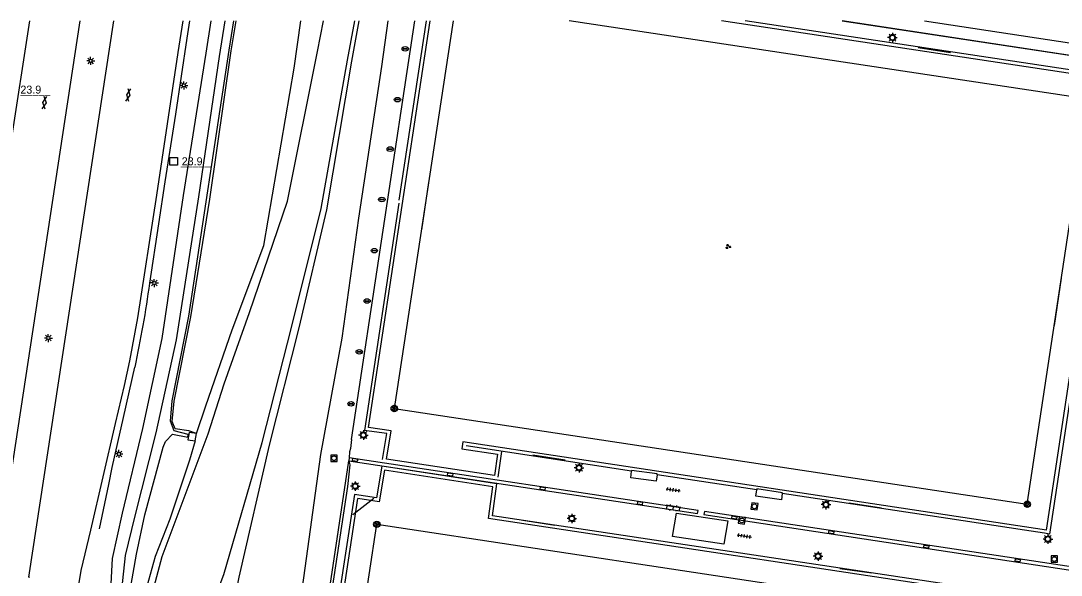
# Model space of a CAD drawing. Extents: x 125000 to 129004, y 397500 to 399008.
# Drawn here: x 126193.2 to 126355.6, y 398913.4 to 399000 of the extents above; entities that cross this region are included whole.
import ezdxf

# ---------------------------------------------------------------- set-up
doc = ezdxf.new("R2010")
doc.units = 0
for name, color, linetype in [('bs-afsc-ballenvanger', 7, 'Continuous'), ('bs-afsc-belijning', 7, 'Continuous'), ('bs-afsc-doel', 7, 'Continuous'), ('bs-afsc-hekwerk laag', 7, 'Continuous'), ('bs-afsc-poort', 7, 'Continuous'), ('bs-afsc-scorebord', 7, 'Continuous'), ('bs-symb-cornervlag', 7, 'Continuous'), ('bs-symb-veldverlichting', 7, 'Continuous'), ('gg-afsc-hekwerk', 7, 'Continuous'), ('gg-bbg-overig bouwwerk', 7, 'Continuous'), ('gg-knt-BGT kruinlijn', 7, 'Continuous'), ('gg-knt-bovenkant onderkant talud', 7, 'Continuous'), ('gg-knt-verharding', 7, 'Continuous'), ('gg-kntw-bovenkant insteek waterloop', 7, 'Continuous'), ('gg-kntw-waterlijn', 7, 'Continuous'), ('gg-kwrk-uitstroombak niveau min 01', 7, 'Continuous'), ('gt-anno-nummer hm paal', 7, 'Continuous'), ('gt-grn-groengrens', 7, 'Continuous'), ('gt-knt-geleideconstructie', 7, 'Continuous'), ('gt-symb-drainageput', 7, 'Continuous'), ('gt-symb-gesloten verharding', 7, 'Continuous'), ('gt-symb-groenvak', 7, 'Continuous'), ('gt-symb-hm paal', 7, 'Continuous'), ('gt-symb-klinker verharding', 7, 'Continuous'), ('gt-symb-kolk center center', 7, 'Continuous'), ('gt-symb-lichtmast', 7, 'Continuous'), ('gt-symb-rioolschacht', 7, 'Continuous'), ('gt-symb-tegel verharding', 7, 'Continuous')]:
    doc.layers.add(name, color=color, linetype=linetype)

# ---------------------------------------------------------------- blocks, each defined once
blk = doc.blocks.new('gt0-KOLKCC')
at = {"layer": 'gt-symb-kolk center center'}
blk.add_lwpolyline([(-0.38, 0.2), (0.37, 0.2), (0.37, -0.2), (-0.38, -0.2)], close=True, dxfattribs=at)
blk = doc.blocks.new('bs0-VELDV')
at = {"layer": 'bs-symb-veldverlichting'}
for p, q in [((-0.38, 0), (-0.75, 0)), ((-0.53, 0.53), (-0.27, 0.27)), ((-0.35, 0.14), (-0.52, 0.22)), ((-0.22, 0.52), (-0.14, 0.35)), ((0, 0.75), (0, 0.38)), ((0.22, 0.52), (0.14, 0.35)), ((0.27, 0.27), (0.53, 0.53)), ((0.35, 0.14), (0.52, 0.22)), ((0.38, 0), (0.75, 0)), ((-0.27, -0.27), (-0.53, -0.53)), ((-0.35, -0.14), (-0.52, -0.22)), ((-0.14, -0.35), (-0.22, -0.52)), ((0, -0.38), (0, -0.75)), ((0.14, -0.35), (0.22, -0.52)), ((0.27, -0.27), (0.53, -0.53)), ((0.35, -0.14), (0.52, -0.22))]:
    blk.add_line(p, q, dxfattribs=at)
blk.add_circle((0, 0), 0.375, dxfattribs=at)
blk = doc.blocks.new('gt0-RS')
at = {"layer": 'gt-symb-rioolschacht'}
blk.add_lwpolyline([(-0.5, -0.5), (0.5, -0.5), (0.5, 0.5), (-0.5, 0.5)], close=True, dxfattribs=at)
blk.add_circle((0, 0), 0.375, dxfattribs=at)
blk = doc.blocks.new('gt0-TEG1')
at = {"layer": 'gt-symb-tegel verharding'}
for p, q in [((-1.12, 0), (1.12, 0)), ((-0.9, -0.25), (-0.9, 0.25)), ((-0.45, -0.25), (-0.45, 0.25)), ((0, -0.25), (0, 0.25)), ((0.45, -0.25), (0.45, 0.25)), ((0.9, -0.25), (0.9, 0.25))]:
    blk.add_line(p, q, dxfattribs=at)
blk = doc.blocks.new('gt0-DPUT')
at = {"layer": 'gt-symb-drainageput'}
for p, q in [((-0.25, 0.05), (0.25, 0.05)), ((0.24, -0.05), (-0.25, -0.05))]:
    blk.add_line(p, q, dxfattribs=at)
for centre, radius, start, end in [((-0.25, 0), 0.0542, 85.4775, 270), ((0.24, 0), 0.0543, 269.9965, 85.474)]:
    blk.add_arc(centre, radius, start, end, dxfattribs=at)
blk.add_ellipse((0, 0), major_axis=(0.502, 0), ratio=0.705307, dxfattribs=at)
blk = doc.blocks.new('bs0-CORNVLG')
at = {"layer": 'bs-symb-cornervlag'}
for p, q in [((-0.34, 0.2), (0.2, -0.34)), ((-0.21, 0.35), (0.34, -0.2)), ((0.03, 0.4), (0.4, 0.03)), ((-0.4, -0.03), (-0.03, -0.4))]:
    blk.add_line(p, q, dxfattribs=at)
blk.add_circle((0, 0), 0.5, dxfattribs=at)
blk = doc.blocks.new('gt0-KL1')
at = {"layer": 'gt-symb-klinker verharding'}
for p, q in [((-1.15, 0.3), (1.15, 0.3)), ((-1, -0.3), (-1, 0.3)), ((-0.5, 0.3), (-0.5, 0.45)), ((0, -0.3), (0, 0.3)), ((0.5, 0.3), (0.5, 0.45)), ((1, -0.3), (1, 0.3)), ((-1.15, -0.3), (1.15, -0.3)), ((-0.5, -0.45), (-0.5, -0.3)), ((0.5, -0.45), (0.5, -0.3))]:
    blk.add_line(p, q, dxfattribs=at)
blk = doc.blocks.new('gt0-GRVAK')
at = {"layer": 'gt-symb-groenvak'}
for p, q in [((-0.11, 0.19), (-0.23, 0.24)), ((-0.18, 0.15), (0.09, 0.15)), ((-0.09, 0.21), (-0.16, 0.32)), ((-0.05, 0.21), (-0.05, 0.39)), ((0, 0.21), (0.06, 0.32)), ((0.01, 0.19), (0.13, 0.24)), ((0.26, -0.05), (0.2, 0.06)), ((0.3, -0.05), (0.3, 0.13)), ((0.35, -0.05), (0.41, 0.06)), ((-0.24, -0.23), (-0.36, -0.18)), ((-0.32, -0.26), (-0.05, -0.26)), ((-0.23, -0.21), (-0.29, -0.09)), ((-0.18, -0.2), (-0.18, -0.02)), ((-0.14, -0.21), (-0.07, -0.09)), ((-0.12, -0.23), (0, -0.18)), ((0.24, -0.07), (0.12, -0.02)), ((0.17, -0.11), (0.44, -0.11)), ((0.37, -0.07), (0.49, -0.02))]:
    blk.add_line(p, q, dxfattribs=at)
blk = doc.blocks.new('gt0-HMpaal')
at = {"layer": 'gt-symb-hm paal'}
blk.add_lwpolyline([(-0.6, 0.6), (0.6, 0.6), (0.6, -0.6), (-0.6, -0.6)], close=True, dxfattribs=at)
blk = doc.blocks.new('gt0-LMAST')
at = {"layer": 'gt-symb-lichtmast'}
for p, q in [((-0.18, 0.17), (-0.45, 0.44)), ((-0.01, 0.25), (-0.01, 0.62)), ((0.17, 0.17), (0.44, 0.44)), ((-0.26, 0), (-0.63, 0)), ((-0.18, -0.18), (-0.45, -0.45)), ((-0.01, -0.25), (-0.01, -0.63)), ((0.44, -0.45), (0.17, -0.18)), ((0.24, 0), (0.62, 0))]:
    blk.add_line(p, q, dxfattribs=at)
blk.add_circle((-0.01, 0), 0.25, dxfattribs=at)
blk = doc.blocks.new('gt0-GESVH1')
at = {"layer": 'gt-symb-gesloten verharding'}
for p, q in [((-0.99, -0.26), (0.01, 0.24)), ((0.01, -0.26), (-0.99, 0.24)), ((0.01, 0.24), (1.01, -0.26)), ((1.01, 0.24), (0.01, -0.26))]:
    blk.add_line(p, q, dxfattribs=at)

msp = doc.modelspace()

# ---------------------------------------------------------------- linework, layer by layer
at = {"layer": 'bs-afsc-ballenvanger'}
for p, q in [((126244.85, 398934.61), (126254.73, 399000)), ((126288.56, 398929.69), (126262.72, 398933.61)), ((126337.94, 398922.28), (126312.09, 398926.17))]:
    msp.add_line(p, q, dxfattribs=at)
for points in [[(126360.24, 398920.79), (126371.06, 398992.37), (126371.08, 398992.46), (126321.44, 399000)], [(126244.69, 398933.21), (126244.52, 398932.68), (126244.45, 398931.77), (126244.42, 398931.27), (126244.56, 398930.69), (126244.22, 398927.26), (126233.22, 398854.66)]]:
    msp.add_lwpolyline(points, dxfattribs=at)
at = {"layer": 'bs-afsc-belijning'}
for points in [[(126260.68, 399000), (126251.51, 398939.46), (126350.34, 398924.51), (126359.87, 398987.75), (126278.82, 399000)], [(126248.79, 398921.38), (126347.65, 398906.42), (126338, 398843.2), (126239.2, 398858.12), (126248.79, 398921.38)]]:
    msp.add_lwpolyline(points, dxfattribs=at)
at = {"layer": 'bs-afsc-doel'}
for p, q in [((126333.31, 398995.82), (126338.35, 398995.07)), ((126256.86, 398974.76), (126255.74, 398967.36)), ((126355.62, 398959.84), (126354.55, 398952.42)), ((126278.18, 398931.4), (126273.12, 398932.2)), ((126327.58, 398923.92), (126322.52, 398924.7)), ((126271.57, 398922.01), (126276.57, 398921.24)), ((126321.06, 398914.49), (126326.09, 398913.78))]:
    msp.add_line(p, q, dxfattribs=at)
at = {"layer": 'bs-afsc-hekwerk laag'}
for p, q in [((126252.28, 398972), (126256.53, 399000)), ((126252.22, 398971.55), (126246.85, 398936.03)), ((126268.26, 398932.77), (126267.66, 398928.76)), ((126308.1, 398926.78), (126292.53, 398929.11)), ((126242, 398904.04), (126245.34, 398926.03)), ((126349.88, 398920.46), (126337.94, 398922.28))]:
    msp.add_line(p, q, dxfattribs=at)
for points in [[(126359.21, 398955.62), (126364.59, 398991.18), (126306.3, 399000)], [(126359.15, 398955.2), (126353.8, 398919.85), (126353, 398919.98)], [(126249.69, 398931.51), (126250.37, 398935.54), (126246.82, 398936.05)], [(126352.26, 398909.83), (126266.82, 398922.73), (126267.52, 398927.71), (126249.56, 398930.47), (126248.74, 398925.52), (126245.32, 398926.01)]]:
    msp.add_lwpolyline(points, dxfattribs=at)
at = {"layer": 'bs-afsc-poort'}
for p, q in [((126244.85, 398934.61), (126244.69, 398933.21)), ((126353, 398919.98), (126349.88, 398920.46))]:
    msp.add_line(p, q, dxfattribs=at)
at = {"layer": 'bs-afsc-scorebord'}
msp.add_line((126248.34, 398925.4), (126245.02, 398922.88), dxfattribs=at)
at = {"layer": 'gg-afsc-hekwerk'}
for p, q in [((126244.85, 398934.61), (126254.73, 399000)), ((126321.44, 399000), (126371.08, 398992.46)), ((126244.85, 398934.61), (126244.69, 398933.21)), ((126244.52, 398932.68), (126244.45, 398931.77)), ((126244.69, 398933.21), (126244.52, 398932.68)), ((126244.45, 398931.77), (126244.42, 398931.27)), ((126244.42, 398931.27), (126244.56, 398930.69))]:
    msp.add_line(p, q, dxfattribs=at)
msp.add_lwpolyline([(126244.56, 398930.69), (126244.22, 398927.26), (126233.22, 398854.66)], dxfattribs=at)
at = {"layer": 'gg-bbg-overig bouwwerk'}
for points in [[(126292.53, 398929.11), (126292.4, 398928.11), (126288.43, 398928.62), (126288.56, 398929.69)], [(126292.53, 398929.11), (126292.54, 398929.24), (126288.57, 398929.76), (126288.56, 398929.69)], [(126312.09, 398926.17), (126311.95, 398925.19), (126307.96, 398925.79), (126308.1, 398926.78)], [(126312.09, 398926.17), (126312.11, 398926.32), (126308.12, 398926.93), (126308.1, 398926.78)], [(126303.56, 398921.91), (126302.96, 398918.29), (126294.97, 398919.49), (126295.57, 398923.11), (126303.56, 398921.91)]]:
    msp.add_lwpolyline(points, dxfattribs=at)
at = {"layer": 'gg-knt-BGT kruinlijn'}
for points in [[(126211.12, 398796.76), (126213.8, 398804.98), (126217.29, 398818.65), (126218.75, 398842.29), (126220.71, 398866.08), (126222.04, 398889.56), (126220.71, 398902.4), (126224.92, 398913.56), (126230.87, 398934.16), (126235.52, 398952.3), (126240.11, 398970.7), (126244.21, 398993.87), (126245.36, 399000)], [(126212.79, 398796.85), (126214.45, 398804.72), (126217.92, 398818.54), (126219.55, 398842.15), (126221.57, 398866.06), (126224.03, 398889.12), (126224.94, 398901.72), (126227.27, 398913.12), (126232.02, 398933.76), (126236.66, 398952.06), (126241, 398970.48), (126244.91, 398993.71), (126246.02, 399000)], [(126220.61, 398935.54), (126222.08, 398939.86), (126226.2, 398951.74), (126231.17, 398964.91), (126235.87, 398992.58), (126236.91, 399000)]]:
    msp.add_lwpolyline(points, dxfattribs=at)
at = {"layer": 'gg-knt-bovenkant onderkant talud'}
for points in [[(126204.12, 398801.18), (126207.27, 398807.9), (126210.77, 398815.47), (126211.54, 398819.18), (126211.15, 398842.84), (126211.31, 398866.36), (126211.15, 398890.1), (126212.52, 398897.68), (126212.58, 398906.21), (126215.25, 398916.33), (126222.46, 398935.51), (126224.93, 398943.33), (126228.92, 398954.45), (126234.85, 398971.83), (126239.51, 398995.23), (126240.48, 399000)], [(126220.17, 398796.67), (126221.21, 398803.52), (126223.59, 398817.57), (126227.06, 398840.65), (126230.5, 398865.35), (126232.89, 398887.78), (126236.04, 398900.78), (126237.19, 398911.52), (126240.04, 398932.3), (126243.4, 398950.47), (126246, 398969.2), (126249.56, 398992.89), (126250.56, 399000)]]:
    msp.add_lwpolyline(points, dxfattribs=at)
at = {"layer": 'gg-knt-verharding'}
for p, q in [((126191.65, 398980.76), (126194.59, 399000)), ((126247.49, 398936.52), (126257.14, 399000)), ((126232.65, 398853.51), (126244.42, 398931.27))]:
    msp.add_line(p, q, dxfattribs=at)
for points in [[(126189.19, 398913.89), (126189.31, 398913.86), (126202.47, 399000)], [(126194.6, 398913.09), (126194.48, 398913.11), (126207.72, 399000)], [(126202.26, 398911.93), (126202.63, 398914.18), (126204.12, 398920.45), (126207.99, 398937.14), (126209.4, 398943.06), (126210.24, 398946.92), (126211.46, 398953.61), (126214.44, 398972.78), (126217.78, 398995.05), (126218.54, 399000)], [(126353.35, 398920.49), (126363.94, 398990.71), (126302.62, 399000)], [(126353.35, 398920.49), (126262.21, 398934.27), (126262.05, 398933.17), (126267.64, 398932.33), (126267.15, 398928.99), (126250.29, 398931.53), (126251.02, 398935.97), (126247.49, 398936.52)], [(126244.42, 398931.27), (126298.86, 398923.05), (126298.94, 398923.54), (126244.45, 398931.77)], [(126351.64, 398909.37), (126266.2, 398922.29), (126266.9, 398927.24), (126250, 398929.81), (126249.17, 398924.89), (126245.83, 398925.4)], [(126351.64, 398909.37), (126340.99, 398839.15), (126235.21, 398855.23), (126245.83, 398925.4)], [(126359.25, 398914.42), (126299.92, 398923.4), (126299.86, 398922.9), (126359.17, 398913.93)]]:
    msp.add_lwpolyline(points, dxfattribs=at)
at = {"layer": 'gg-kntw-bovenkant insteek waterloop'}
for points in [[(126194.82, 398801.92), (126195.6, 398809.24), (126198.28, 398830.35), (126200.6, 398852.35), (126202.6, 398870.53), (126205.11, 398890.25), (126205.86, 398898.74), (126207.18, 398909.1), (126207.54, 398916.03), (126209.09, 398923.11), (126212.27, 398936.35), (126215.29, 398950.37), (126218.62, 398972.72), (126222.13, 398994.95), (126222.9, 399000)], [(126220.61, 398935.54), (126219.44, 398936), (126217.29, 398936.28), (126216.83, 398937.44), (126217.16, 398940.59), (126219.76, 398953.77), (126222.73, 398972.16), (126226.06, 398995.29), (126226.83, 399000)], [(126220.43, 398934.4), (126219.54, 398931.42), (126216.45, 398922.19), (126214.2, 398916.33), (126212.1, 398908.85), (126211.16, 398906.68), (126211, 398902.92), (126211.53, 398899.33), (126211.08, 398897.23), (126209.87, 398890.85), (126209.95, 398870.87), (126210.44, 398853.87), (126209.89, 398831.34), (126210.31, 398819.41), (126209.59, 398816.36), (126207.78, 398812.31), (126204.23, 398806.02)]]:
    msp.add_lwpolyline(points, dxfattribs=at)
at = {"layer": 'gg-kntw-waterlijn'}
for points in [[(126196.93, 398798.36), (126198, 398808.89), (126200.69, 398830.06), (126202.99, 398851.76), (126204.83, 398870.42), (126207.04, 398890.34), (126207.7, 398898.07), (126208.71, 398908.69), (126209.56, 398916.5), (126211, 398922.5), (126214.32, 398935.67), (126217.53, 398950.17), (126221, 398972.49), (126224.24, 398994.42), (126225.1, 399000)], [(126207.72, 398831.87), (126207.75, 398853.51), (126207.53, 398871.49), (126208.31, 398891.11), (126209.28, 398897.74), (126209.44, 398898.91), (126210.05, 398909.92), (126211.26, 398916.74), (126212.57, 398922.85), (126215.41, 398933.41), (126215.77, 398934.32), (126216.91, 398935.43), (126219.29, 398935.01), (126219.35, 398935.4), (126217.16, 398935.99), (126216.59, 398937.48), (126216.86, 398940.68), (126219.45, 398953.86), (126225.75, 398995.42), (126226.46, 399000)]]:
    msp.add_lwpolyline(points, dxfattribs=at)
at = {"layer": 'gg-kwrk-uitstroombak niveau min 01'}
msp.add_line((126220.43, 398934.4), (126220.61, 398935.54), dxfattribs=at)
msp.add_lwpolyline([(126220.61, 398935.54), (126219.48, 398935.74), (126219.29, 398934.59), (126220.43, 398934.4)], dxfattribs=at)
at = {"layer": 'gt-grn-groengrens'}
msp.add_line((126334.28, 399000), (126374.06, 398993.91), dxfattribs=at)
at = {"layer": 'gt-knt-geleideconstructie'}
for points in [[(126213.35, 398959.03), (126214.78, 398968.28), (126215.76, 398974.88), (126217.39, 398985.42), (126219.2, 398997.28), (126219.6, 399000)], [(126205.51, 398920.7), (126206.93, 398927.61), (126207.47, 398930.24), (126208.36, 398934.15), (126209.26, 398938.05), (126211.03, 398945.9)]]:
    msp.add_lwpolyline(points, dxfattribs=at)
msp.add_arc((126033.5, 398984.02), 181.58, 347.8817, 352.0884, dxfattribs=at)

# ---------------------------------------------------------------- block references
at = {"layer": 'bs-symb-cornervlag'}
for p in [(126251.51, 398939.46), (126350.34, 398924.51), (126248.79, 398921.38)]:
    msp.add_blockref('bs0-CORNVLG', p, dxfattribs=at)
at = {"layer": 'bs-symb-veldverlichting'}
for p in [(126329.28, 398997.37), (126246.69, 398935.32), (126280.35, 398930.22), (126245.42, 398927.34), (126318.9, 398924.45), (126279.23, 398922.29), (126353.55, 398919.08), (126317.67, 398916.41)]:
    msp.add_blockref('bs0-VELDV', p, dxfattribs=at)
at = {"layer": 'gt-symb-drainageput'}
for p in [(126253.22, 398995.62), (126252.02, 398987.69), (126250.87, 398979.97), (126249.57, 398972.1), (126248.4, 398964.11), (126247.26, 398956.24), (126246.05, 398948.32), (126244.76, 398940.2)]:
    msp.add_blockref('gt0-DPUT', p, dxfattribs=at)
at = {"layer": 'gt-symb-gesloten verharding'}
for p, rotation in [((126210, 398988.42), -99.72596567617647), ((126196.91, 398987.22), -98.10579358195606)]:
    msp.add_blockref('gt0-GESVH1', p, dxfattribs=dict(at, rotation=rotation))
at = {"layer": 'gt-symb-groenvak'}
msp.add_blockref('gt0-GRVAK', (126303.63, 398964.74), dxfattribs=at)
at = {"layer": 'gt-symb-hm paal'}
msp.add_blockref('gt0-HMpaal', (126217.09, 398978.08), dxfattribs=at)
at = {"layer": 'gt-symb-klinker verharding', "rotation": -8.624228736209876}
msp.add_blockref('gt0-KL1', (126295.07, 398923.93), dxfattribs=at)
at = {"layer": 'gt-symb-kolk center center'}
for p, rotation in [((126245.4, 398931.43), -8.680850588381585), ((126260.24, 398929.16), -8.624228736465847), ((126274.67, 398926.97), -8.567589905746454), ((126289.87, 398924.68), 171.43241009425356), ((126304.59, 398922.43), 171.31914941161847), ((126319.72, 398920.14), 171.3757712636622), ((126334.56, 398917.89), -8.45426172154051), ((126348.85, 398915.76), 171.48906580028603)]:
    msp.add_blockref('gt0-KOLKCC', p, dxfattribs=dict(at, rotation=rotation))
at = {"layer": 'gt-symb-lichtmast'}
for p in [(126204.12, 398993.75), (126218.67, 398989.92), (126214.06, 398959.06), (126197.51, 398950.47), (126208.54, 398932.37)]:
    msp.add_blockref('gt0-LMAST', p, dxfattribs=at)
at = {"layer": 'gt-symb-rioolschacht'}
for p in [(126242.1, 398931.7), (126354.55, 398915.95)]:
    msp.add_blockref('gt0-RS', p, dxfattribs=at)
for p, rotation in [((126307.74, 398924.18), -97.93555037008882), ((126305.77, 398921.99), -7.757425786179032)]:
    msp.add_blockref('gt0-RS', p, dxfattribs=dict(at, rotation=rotation))
at = {"layer": 'gt-symb-tegel verharding', "rotation": -8.624228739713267}
for p in [(126295.06, 398926.76), (126306.17, 398919.55)]:
    msp.add_blockref('gt0-TEG1', p, dxfattribs=at)

# ---------------------------------------------------------------- texts
at = {"layer": 'gt-anno-nummer hm paal'}
for p in [(126193.14, 398988.63), (126218.33, 398977.44)]:
    msp.add_text('23.9', height=1.25, dxfattribs=at).set_placement(p)
at = {"layer": 'gt-symb-hm paal'}
for p in [(126193.14, 398988.63), (126218.17, 398977.47)]:
    msp.add_text('_____', height=1.25, dxfattribs=at).set_placement(p)

doc.saveas('drawing.dxf')
